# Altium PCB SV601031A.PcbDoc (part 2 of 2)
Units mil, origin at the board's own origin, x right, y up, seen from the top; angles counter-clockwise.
Board outline 4000 x 2000 mil, 6 copper layers (Top Layer, MidLayer1, MidLayer2, Mid-Layer 3, Mid-Layer 4, Bottom Layer), stack 60.8 mil thick; 81 components, 26 nets, 217 pads, 227 vias.
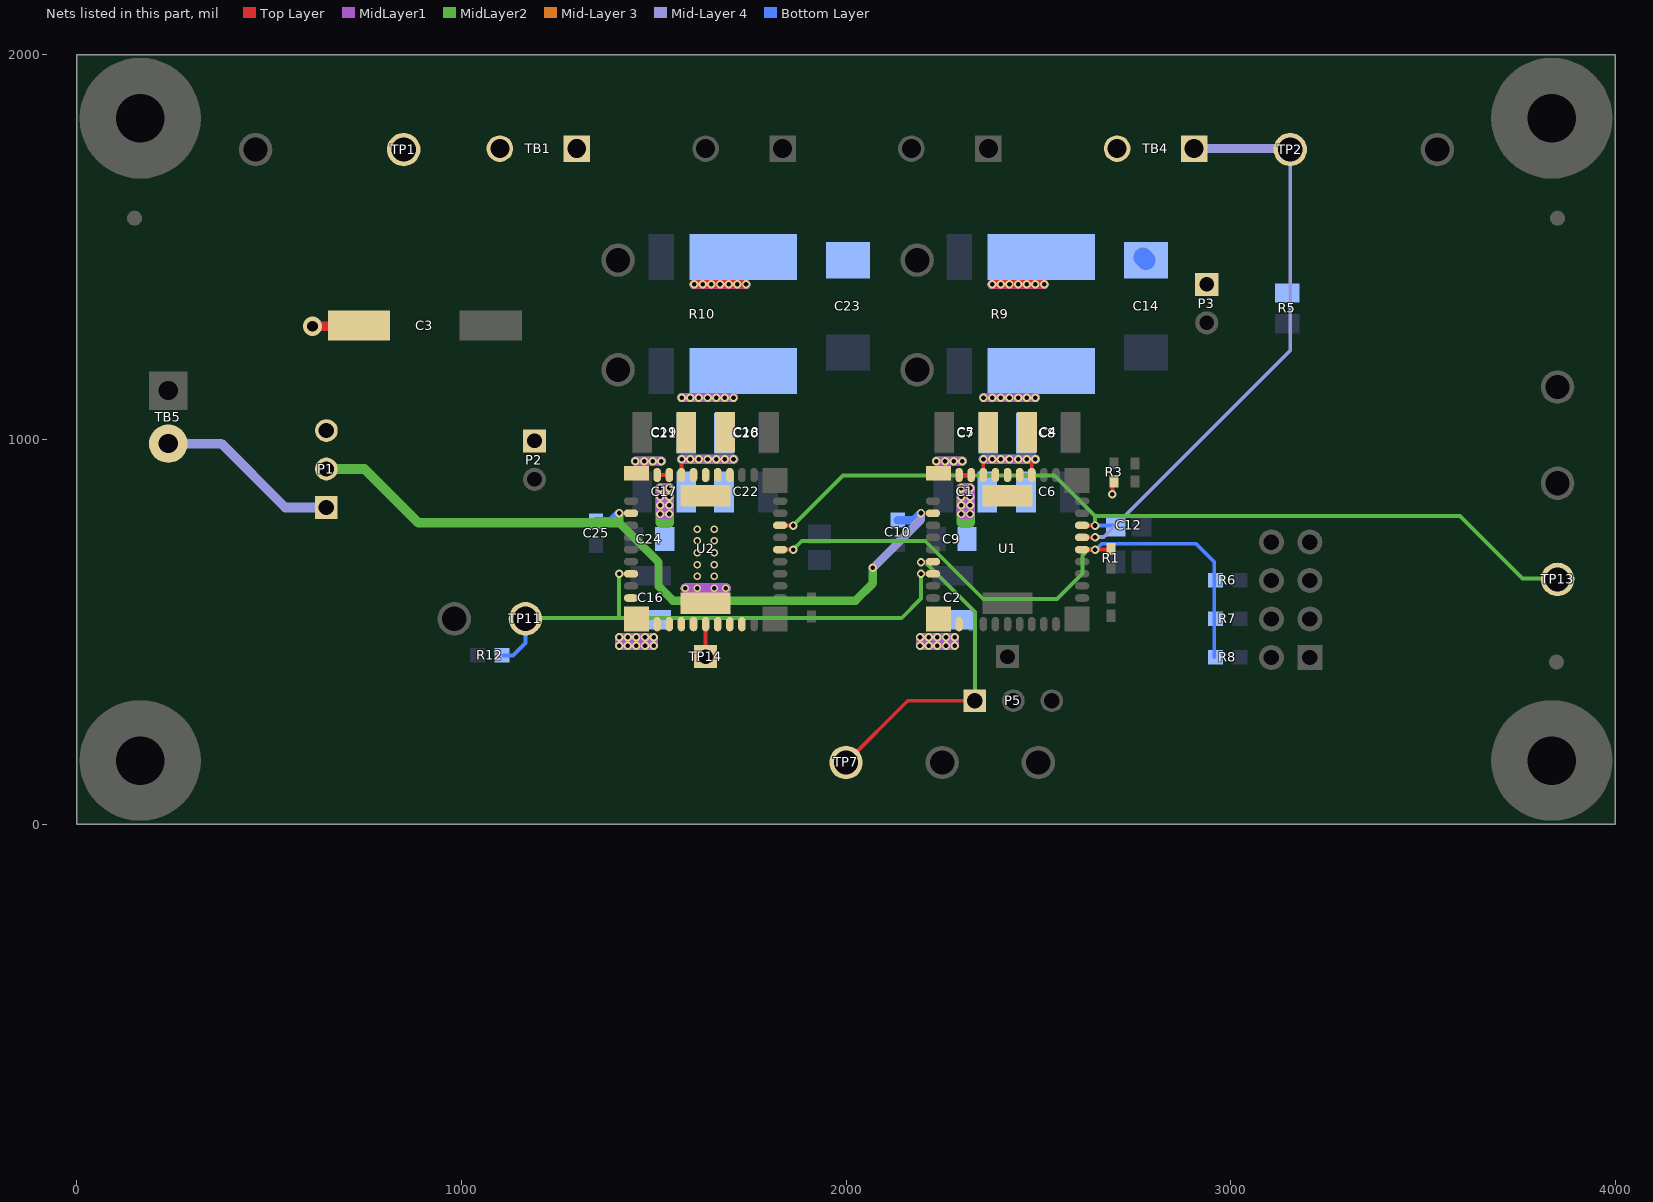
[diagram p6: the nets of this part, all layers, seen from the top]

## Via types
v1: diameter 22/22/22/22/22/22 (per signal layer), hole 12, Top Layer to Bottom Layer, 198 vias
v2: diameter 19.68, hole 11.81, Top Layer to Bottom Layer, 28 vias
v3: diameter 50, hole 28, Top Layer to Bottom Layer, 1 vias

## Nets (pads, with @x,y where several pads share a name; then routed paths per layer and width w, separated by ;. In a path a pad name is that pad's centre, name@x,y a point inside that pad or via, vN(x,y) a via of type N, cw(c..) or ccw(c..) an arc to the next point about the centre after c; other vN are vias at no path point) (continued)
PH2: TP14.1 U2.10 U2.13 U2.14 U2.15 U2.16 U2.17 U2.18 U2.19 U2.42 | length 604.6
  Top Layer w10: TP14.1@1635,443.5 U2.16@1635,519.6
  MidLayer1 w25: v2(1582.15,613.11) v2(1612.85,613.11) v2(1657.15,613.11) v2(1687.85,613.11)
  MidLayer2 w25: v2(1582.15,613.11) v2(1612.85,613.11) v2(1657.15,613.11) v2(1687.85,613.11)
  Mid-Layer 3 w25: v2(1582.15,613.11) v2(1612.85,613.11) v2(1657.15,613.11) v2(1687.85,613.11)
  Mid-Layer 4 w25: v2(1582.15,613.11) v2(1612.85,613.11) v2(1657.15,613.11) v2(1687.85,613.11)
  Bottom Layer w25: v2(1582.15,613.11) v2(1612.85,613.11) v2(1657.15,613.11) v2(1687.85,613.11)
  other v2: 1612.85,643.82 1657.15,643.82 1612.85,674.52 1657.15,674.52 1612.85,705.23 1657.15,705.23 1612.85,735.94 1657.15,735.94 1612.85,766.65 1657.15,766.65
PRE_VOUT: C4.1 C5.1 C6.1 C7.1 C8.1 R9.4 U1.34 U1.35 U1.36 U1.37 U1.38 U1.41 | length 1014.7
  Top Layer w10: U1.38@2357.01,907.4 2357.01,948.5 v1(2357.5,948.5) v1(2380,948.5) v1(2402.5,948.5) v1(2425,948.5) v1(2447.5,948.5) v1(2470,948.5) ; U1.34@2482.99,907.4 2482.99,948.5 v1(2492.5,948.5)
  MidLayer1 w23: v1(2357.5,948.5) v1(2380,948.5) v1(2402.5,948.5) v1(2425,948.5) v1(2447.5,948.5) v1(2470,948.5) v1(2492.5,948.5) ; v1(2357.5,1108.5) v1(2380,1108.5) v1(2402.5,1108.5) v1(2425,1108.5) v1(2447.5,1108.5) v1(2470,1108.5) v1(2492.5,1108.5)
  MidLayer2 w23: v1(2357.5,948.5) v1(2380,948.5) v1(2402.5,948.5) v1(2425,948.5) v1(2447.5,948.5) v1(2470,948.5) v1(2492.5,948.5) ; v1(2357.5,1108.5) v1(2380,1108.5) v1(2402.5,1108.5) v1(2425,1108.5) v1(2447.5,1108.5) v1(2470,1108.5) v1(2492.5,1108.5)
  Mid-Layer 4 w22: v1(2357.5,1108.5) v1(2380,1108.5) v1(2402.5,1108.5) v1(2425,1108.5) v1(2447.5,1108.5) v1(2470,1108.5) v1(2492.5,1108.5)
  Mid-Layer 4 w25: v1(2357.5,948.5) v1(2380,948.5) v1(2402.5,948.5) v1(2425,948.5) v1(2447.5,948.5) v1(2470,948.5) v1(2492.5,948.5)
PRE_VOUT2: C18.1 C19.1 C20.1 C21.1 C22.1 R10.4 U2.34 U2.35 U2.36 U2.37 U2.38 U2.41 | length 986.6
  Top Layer w10: U2.38@1572.01,907.4 1572.01,948.5 v1(1572.5,948.5) v1(1595,948.5) v1(1617.5,948.5) v1(1640,948.5) v1(1662.5,948.5) v1(1685,948.5) v1(1707.5,948.5)
  MidLayer1 w23: v1(1572.5,948.5) v1(1595,948.5) v1(1617.5,948.5) v1(1640,948.5) v1(1662.5,948.5) v1(1685,948.5) v1(1707.5,948.5) ; v1(1572.5,1108.5) v1(1595,1108.5) v1(1617.5,1108.5) v1(1640,1108.5) v1(1662.5,1108.5) v1(1685,1108.5) v1(1707.5,1108.5)
  MidLayer2 w23: v1(1572.5,948.5) v1(1595,948.5) v1(1617.5,948.5) v1(1640,948.5) v1(1662.5,948.5) v1(1685,948.5) v1(1707.5,948.5) ; v1(1572.5,1108.5) v1(1595,1108.5) v1(1617.5,1108.5) v1(1640,1108.5) v1(1662.5,1108.5) v1(1685,1108.5) v1(1707.5,1108.5)
  Mid-Layer 4 w22: v1(1572.5,1108.5) v1(1595,1108.5) v1(1617.5,1108.5) v1(1640,1108.5) v1(1662.5,1108.5) v1(1685,1108.5) v1(1707.5,1108.5)
  Mid-Layer 4 w25: v1(1572.5,948.5) v1(1595,948.5) v1(1617.5,948.5) v1(1640,948.5) v1(1662.5,948.5) v1(1685,948.5) v1(1707.5,948.5)
PVIN: C1.1 C2.1 C3.1 C9.1 C16.1 C17.1 C24.1 P1.3 P2.1 R3.2 TB1.1 TB1.2 TP1.1 U1.1 U1.11 U1.12 U1.39 U1.40 U2.1 U2.11 U2.12 U2.39 U2.40 | length 2262.9
  Top Layer w10: U2.40@1509.02,907.4 U2.39@1540.51,907.4 ; U1.11@2215,533.38 U1.11@2239.88,533.38 ; U1.40@2294.02,907.4 U1.39@2325.51,907.4 ; v1@2692.5,863.5 R3.2@2692.5,888.5
  Top Layer w25: v3@619,1294 731.74,1294 C3.1@733.74,1296
  MidLayer1 w22: v1@2192.5,483.5 v1(2192.5,463.5) v1(2215,463.5) v1(2237.5,463.5) v1(2260,463.5) v1(2282.5,463.5) v1(2282.5,486) v1(2260,486) v1(2237.5,486) v1(2215,486) v1(2192.5,486) ; v1(1410,463.5) v1(1410,486) v1(1432.5,486) v1(1455,486) v1(1477.5,486) v1(1500,486) v1(1500,463.5) v1(1477.5,463.5) v1(1455,463.5) v1(1432.5,463.5) v1(1410,463.5)
  MidLayer1 w23: v1(1452.5,943.5) v1(1520,943.5) ; v1(2235,943.5) v1(2257.5,943.5) v1(2280,943.5) v1(2302.5,943.5)
  MidLayer1 w25: v1@1517.5,870.5 v1(1517.5,851) v1(1517.5,828.5) v1(1517.5,806) v1(1540,806) v1(1540,828.5) v1(1540,851) v1(1540,873.5) v1(1517.5,873.5) ; v1@2300,871 v1(2300,851) v1(2300,828.5) v1(2300,806) v1(2322.5,806) v1(2322.5,828.5) v1(2322.5,851) v1(2322.5,873.5) v1(2300,873.5)
  MidLayer2 w22: v1(2192.5,486) v1(2192.5,463.5) v1(2215,463.5) v1(2237.5,463.5) v1(2260,463.5) v1(2282.5,463.5) v1(2282.5,486) v1(2260,486) v1(2237.5,486) v1(2215,486) v1@2195,486 ; v1(1410,463.5) v1(1410,486) v1(1432.5,486) v1(1455,486) v1(1477.5,486) v1(1500,486) v1(1500,463.5) v1(1477.5,463.5) v1(1455,463.5) v1(1432.5,463.5) v1(1410,463.5)
  MidLayer2 w23: v1(1452.5,943.5) v1(1497.5,943.5) v1(1520,943.5) ; v1(2235,943.5) v1(2257.5,943.5) v1(2280,943.5) v1(2302.5,943.5)
  MidLayer2 w25: v1@1517.5,872.5 v1(1517.5,851) v1(1517.5,828.5) v1(1517.5,806) 1517.5,783.5 1540,783.5 v1(1540,806) v1(1540,828.5) v1(1540,851) v1(1540,873.5) v1(1517.5,873.5) ; v1@2300,872 v1(2300,851) v1(2300,828.5) v1(2300,806) 2300,783.5 2322.5,783.5 v1(2322.5,806) v1(2322.5,828.5) v1(2322.5,851) v1(2322.5,873.5) v1(2300,873.5)
  Bottom Layer w22: v1(2235,943.5) v1(2257.5,943.5) v1(2280,943.5) v1(2302.5,943.5)
  other v1: 2692.5,857.5 1475,943.5
  other v3: 613,1294
PWRGD: R12.1 TP11.1 U1.8 U2.8 | length 1421.9
  Top Layer w10: v1@1410,650.51 U2.8@1441.1,650.51 ; v1@2195.49,650.51 U1.8@2226.1,650.51
  MidLayer2 w10: TP11.1@1169,536 1410,536 ; v1(1410,651) 1410,536 ; v1(2195,651) 2195,586 2145,536 1410,536
  Bottom Layer w10: R12.1@1109,438.5 1134,438.5 1166.5,471 TP11.1@1166.5,533.5
SS/TR: C12.1 TP13.1 U1.28 U2.28 | length 2346.7
  Top Layer w10: U2.28@1828.9,776.49 v1@1862.5,776.49 ; U1.28@2613.9,776.49 v1@2647.01,776.49
  MidLayer2 w10: v1(1862.5,776) 1992.5,906 2542.5,906 2647.5,801 ; v1(2647.5,776) 2647.5,801 ; TP13.1@3880,636 3890,638.5 3758.5,638.5 3596,801 2647.5,801
  Bottom Layer w10: v1(2647.5,776) C12.1@2700,776
SYNC_OUT: P5.1 TP7.1 U1.7 | length 874.3
  Top Layer w10: TP7.1@2000,160 2160.5,320.5 P5.1@2335,320.5 ; v1(2195,681) 2196,682 U1.7@2226.1,682
  MidLayer2 w10: v1(2195,681) 2205,681 2335,551 P5.1@2335,320.5 P5.1@2335,303.5
VADJ: R1.2 R6.2 R7.2 R8.2 U1.26 U2.26 | length 1633.5
  Top Layer w10: U2.26@1828.9,713.5 v1(1862.5,713.5) ; U1.26@2613.9,713.5 v1(2647.5,713.5) 2692.5,713.5 R1.2@2692.5,716
  MidLayer2 w10: v1(1862.5,713.5) 1885,736 2206,736 2357,585 2549,585 2615,651 2615,698.5 2630,713.5 v1(2647.5,713.5)
  Bottom Layer w10: v1@2650,713.5 2665,728.5 2910,728.5 2957.5,681 R8.2@2957.5,433.5
VBIAS: P1.1 TB5.2 | length 479.8
  Mid-Layer 4 w25: TB5.2@238,989 376,989 542,823 P1.1@649,823
VIN: C10.1 C25.1 P1.2 U1.3 U2.3 | length 2075.2
  Top Layer w10: v1@1410.51,807.99 U2.3@1441.1,807.99 ; v1@2195,807.99 U1.3@2226.1,807.99
  MidLayer2 w22: v1(1410,808.5) 1410,783.5 1512.5,681 1512.5,618.5 1550,581 2025,581 2070,626 v1(2070,666)
  MidLayer2 w25: P1.2@649,923 748,923 887.5,783.5 1410,783.5
  Mid-Layer 4 w22: v1(2070,666) 2195,791 v1(2195,808.5)
  Bottom Layer w22: C25.1@1350,787.5 1389,787.5 v1(1410,808.5) ; C10.1@2135,790 2176.5,790 v1(2195,808.5)
VOUT: C14.1 C23.1 P3.1 R5.1 R9.2 R10.2 TB4.1 TB4.2 TP2.1 U1.27 | length 3157.1
  Top Layer w10: U1.27@2613.9,745 2647.5,745 v1(2647.5,746)
  Top Layer w22: v1(1605,1403) v1(1627.5,1403) v1(1650,1403) v1(1672.5,1403) v1(1695,1403) v1(1717.5,1403) v1(1740,1403) ; v1(2380,1403) v1(2402.5,1403) v1(2425,1403) v1(2447.5,1403) v1(2470,1403) v1(2492.5,1403) v1(2515,1403)
  MidLayer1 w23: v1(1605,1403) v1(1627.5,1403) v1(1650,1403) v1(1672.5,1403) v1(1695,1403) v1(1717.5,1403) v1(1740,1403) ; v1(2380,1403) v1(2402.5,1403) v1(2425,1403) v1(2447.5,1403) v1(2470,1403) v1(2492.5,1403) v1(2515,1403)
  MidLayer2 w23: v1(1605,1403) v1(1627.5,1403) v1(1650,1403) v1(1672.5,1403) v1(1695,1403) v1(1717.5,1403) v1(1740,1403) ; v1(2380,1403) v1(2402.5,1403) v1(2425,1403) v1(2447.5,1403) v1(2470,1403) v1(2492.5,1403) v1(2515,1403)
  Mid-Layer 3 w23: v1(1605,1403) v1(1627.5,1403) v1(1650,1403) v1(1672.5,1403) v1(1695,1403) v1(1717.5,1403) v1(1740,1403) ; v1(2380,1403) v1(2402.5,1403) v1(2425,1403) v1(2447.5,1403) v1(2470,1403) v1(2492.5,1403) v1(2515,1403)
  Mid-Layer 4 w10: v1(2647.5,746) 2670,746 3155,1231 TP2.1@3155,1753.5
  Mid-Layer 4 w23: v1(1605,1403) v1(1627.5,1403) v1(1650,1403) v1(1672.5,1403) v1(1695,1403) v1(1717.5,1403) v1(1740,1403) ; v1(2380,1403) v1(2402.5,1403) v1(2425,1403) v1(2447.5,1403) v1(2470,1403) v1(2492.5,1403) v1(2515,1403) ; TB4.1@2895,1756 3152.5,1756 TP2.1@3155,1753.5
  Bottom Layer w23: v1(1605,1403) v1(1627.5,1403) v1(1650,1403) v1(1672.5,1403) v1(1695,1403) v1(1717.5,1403) v1(1740,1403) ; v1(2380,1403) v1(2402.5,1403) v1(2425,1403) v1(2447.5,1403) v1(2470,1403) v1(2492.5,1403) v1(2515,1403)
  Bottom Layer w50: C14.1@2772.5,1473.5 C14.1@2780,1466
pads on no net: FID1.1 FID2.1 FID3.1 H1.1 H2.1 H3.1 H4.1 LBL1.0 P4.8 SH-J1.0 SH-J2.0 SH-J3.0 U1.4 U1.5 U1.6 U1.9 U1.24 U2.4 U2.5 U2.6 U2.7 U2.9 U2.24 U2.27

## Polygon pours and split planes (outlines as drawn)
AGND on Top Layer "Top-AGND" (solid, remove dead copper, pour order 119): 20,1978 3980,1978 3980,18 20,18
PGND on Top Layer "Top-PGND 1" (solid, remove dead copper, pour order 118): 20,1973 20,967 2632.5,967 2662.5,999.19 2662.5,1973
PGND on Top Layer "Top-PGND" (solid, remove dead copper, pour order 117): 1719.74,927.56 1719.74,822.3 1712.74,815.3 1562.74,815.3 1562.74,792.8 1712.74,792.8 1719.74,785.8 1719.74,587.8 1751.24,556.8 1751.24,442.8 1867.74,442.8 1867.74,565.3 1807.74,565.3 1797.74,575.3 1797.74,856.8 2102.74,856.8 2102.74,1072.8 1745.24,1072.8 1745.24,952.56
PVIN on Top Layer "Top-PVIN 1" (solid, remove dead copper, pour order 116): 1328.71,956.78 1528.08,956.78 1553,931.42 1553,619.51 1541.54,607.84 1473.25,607.84 1473.25,850.27 1464.28,859.4 1410.95,859.4 1410.95,566.26 1513.13,566.26 1513.13,442 1328.71,442
PVIN on Top Layer "Top-PVIN 2" (solid, remove dead copper, pour order 115): 2113,956 2312.83,956 2335.31,933.24 2335.31,617.1 2326.32,607.99 2257.88,607.99 2257.88,849.78 2248.88,858.88 2195.43,858.88 2195.43,566.52 2297.84,566.52 2297.84,442.59 2113,442.59
PGND on Top Layer "Top-PGND 2" (solid, remove dead copper, pour order 114): 2504.63,928.06 2504.63,822.76 2497.63,815.76 2345.13,815.76 2345.13,793.26 2497.63,793.26 2504.63,786.26 2504.63,588.26 2536.13,557.26 2536.13,443.26 2652.63,443.26 2652.63,565.76 2592.63,565.76 2582.63,575.76 2582.63,857.26 2662.63,857.26 2662.63,1073.26 2530.13,1073.26 2530.13,953.06
PRE_VOUT2 on Top Layer "Top-$$$2" (solid, remove dead copper, pour order 113): 1563,822 1563,934.5 1533,964.5 1533,1129.5 1735.5,1129.5 1735.5,959.5 1708,932 1708,822
PRE_VOUT on Top Layer "Top-$$$" (solid, remove dead copper, pour order 112): 2347.5,823.15 2347.5,935.65 2317.5,965.65 2317.5,1130.65 2520,1130.65 2520,960.65 2492.5,933.15 2492.5,823.15
PH2 on Top Layer "Top-PH2" (solid, remove dead copper, pour order 57): 1711,580 1711,785.5 1563.5,785.5 1563.5,607 1553.5,597 1423.5,597 1423.5,577 1521.5,577 1531.5,567 1531.5,500.5 1740.5,500.5 1740.5,550.5
PH on Top Layer "Top-PH" (solid, remove dead copper, pour order 56): 2495,580.5 2495,786 2347.5,786 2347.5,607.5 2337.5,597.5 2207.5,597.5 2207.5,577.5 2305.5,577.5 2315.5,567.5 2315.5,501 2524.5,501 2524.5,551
PGND on MidLayer1 "Layer 2-PGND" (solid, remove dead copper, pour order 122): 20,19 3980,19 3980,1979 20,1979
PH on MidLayer1 "Layer 2-PH" (solid, remove dead copper, pour order 121): 2385,782.2 2455,782.2 2455,601 2385,601
PH2 on MidLayer1 "Layer 2-PH2" (solid, remove dead copper, pour order 120): 1600,781 1670,781 1670,601 1600,601
PGND on MidLayer2 "Layer 3-PGND" (solid, remove dead copper, pour order 125): 20,19 3980,19 3980,1979 20,1979
PH on MidLayer2 "Layer 3-PH" (solid, remove dead copper, pour order 124): 2385,782 2455,782 2455,602 2385,602
PH2 on MidLayer2 "Layer 3-PH2" (solid, remove dead copper, pour order 123): 1600,782 1670,782 1670,602 1600,602
AGND on Mid-Layer 4 "Layer 5-AGND" (solid, remove dead copper, pour order 136): 3980,985 2193,985 2193,20 3980,20
PVIN on Mid-Layer 4 "Layer 5-PVIN" (solid, remove dead copper, pour order 135): 20,-107 2280,-107 2280,358.85 2355,438.71 2355,792.8 2379.75,819.37 2731.25,819.37 2832.5,925.85 3980,925.85 3980,1980 20,1980
PH on Mid-Layer 4 "Layer 5-PH" (solid, remove dead copper, pour order 134): 2385,781 2455,781 2455,602 2385,602
PH2 on Mid-Layer 4 "Layer 5-PH2" (solid, remove dead copper, pour order 133): 1600,781 1600,602 1667.5,602 1667.5,781
PGND on Bottom Layer "Bottom-PGND" (solid, remove dead copper, pour order 146): 18,1981 3978,1981 3978,21 18,21
VOUT on Bottom Layer "Bottom-VOUT" (solid, remove dead copper, pour order 145): 1403,1981 1403,1422 1533.56,1422 1563.68,1387.6 2819.02,1387.6 2864.22,1336 3989,1336 3989,1981
PRE_VOUT2 on Bottom Layer "Bottom-$$$2" (solid, remove dead copper, pour order 144): 1560,1312 1560,944.87 1572.6,932.38 1615.43,932.38 1625.51,922.39 1625.51,810 1728.82,810 1746.46,827.48 1746.46,1064.75 1766.61,1084.73 1849.76,1084.73 1880,1114.7 1880,1312
PRE_VOUT on Bottom Layer "Bottom-$$$1" (solid, remove dead copper, pour order 143): 2345,1312 2345,944.87 2357.6,932.38 2400.45,932.38 2410.53,922.39 2410.53,810 2513.87,810 2531.52,827.48 2531.52,1064.75 2551.68,1084.73 2627.3,1084.73 2652.5,1109.7 2652.5,1312
PVIN on Bottom Layer "Bottom-PVIN 1" (solid, remove dead copper, pour order 142): 1615,921.36 1567.5,921.36 1535,954.46 1440,954.46 1440,929 1495,929 1502.5,921.36 1502.5,712.56 1507.5,707.46 1557.5,707.46 1567.5,717.65 1567.5,804.23 1572.5,809.32 1615,809.32
PVIN on Bottom Layer "Bottom-PVIN 3" (solid, remove dead copper, pour order 141): 2397.21,921 2350.26,921 2318.13,954.1 2224.21,954.1 2224.21,928.64 2278.59,928.64 2286,921 2286,712.2 2290.94,707.1 2340.37,707.1 2350.26,717.29 2350.26,803.87 2355.2,808.96 2397.21,808.96
PVIN on Bottom Layer "Bottom-PVIN 2" (solid, remove dead copper, pour order 140): 2180,557 2180,453 2340,453 2340,557
PVIN on Bottom Layer "Bottom-PVIN" (solid, remove dead copper, pour order 139): 1397.5,557 1397.5,453 1555,453 1555,557
PH2 on Bottom Layer "Bottom-PH2" (solid, remove dead copper, pour order 138): 1670,780 1600,780 1600,603 1670,603
PH on Bottom Layer "Bottom-PH" (solid, remove dead copper, pour order 137): 2455,780 2385,780 2385,603 2455,603
PVIN on Mid-Layer 3 "Layer 4-PVIN" (solid, remove dead copper, pour order 131): 1512.5,1980 20,1980 20,-109 2280,-109 2280,365.23 2340,429.26 2340,800.77 2377.5,840.79 2715,840.79 2715,1387.72 1517.5,1387.72 1512.5,1393.05
AGND on Mid-Layer 3 "Layer 4-AGND" (solid, remove dead copper, pour order 132): 20,20 3980,20 3980,1977.5 20,1977.5
VOUT on Mid-Layer 3 "Layer 4-VOUT" (solid, remove dead copper, pour order 130): 1517.5,1977.5 1517.5,1370.48 1537.5,1348 3975,1348 3975,1977.5
PRE_VOUT on Mid-Layer 3 "Layer 4-$$$" (solid, remove dead copper, pour order 129): 2340,938 2510,938 2510,1119 2340,1119
PRE_VOUT2 on Mid-Layer 3 "Layer 4-$$$2" (solid, remove dead copper, pour order 128): 1557.5,938 1557.5,1119 1722.5,1119 1722.5,938
PH on Mid-Layer 3 "Layer 4-PH" (solid, remove dead copper, pour order 127): 2385,779.51 2455,779.51 2455,602 2385,602
PH2 on Mid-Layer 3 "Layer 4-PH2" (solid, remove dead copper, pour order 126): 1600,779 1670,779 1670,602 1600,602

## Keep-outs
Keep-Out Layer:
  the board outline again, w4
  text ".Layer_Name" at -38,-1627.49 h60

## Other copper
Top Layer:
  text "Top Layer" at -38,-1627.49 h60
MidLayer1:
  text "MidlLayer1" at -9,-1633 h62.5
MidLayer2:
  text "MidlLayer2" at -28,-1633 h62.5
Mid-Layer 3:
  pour cut-out: 3097.5,1811 3212.5,1811 3212.5,1696 3097.5,1696 3097.5,1811
  text "MidlLayer3" at 18,-1633 h62.5
Mid-Layer 4:
  text "MidlLayer4" at 2,-1641 h62.5
Bottom Layer:
  pour cut-out: 3097.5,1811 3212.5,1811 3212.5,1696 3097.5,1696 3097.5,1811
  text "Bottom Layer" at -38,-1627.49 h60

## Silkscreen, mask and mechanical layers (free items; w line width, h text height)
Top Overlay:
  region: 3348.5,118 3348.5,208 3601.5,208 3601.5,118
  lines w5: 1412.5,491 1857.5,491 1857.5,504 1942,504 1942,622 1857.5,622 1857.5,1086 1412.5,1086 1412.5,491 ; 2197.5,491 2642.5,491 2642.5,506 2721,506 2721,750 2642.5,750 2642.5,854 2785,854 2785,974 2642.5,974 2642.5,1086 2197.5,1086 2197.5,491
  lines w8: 1325,1243 1325,1224 1335,1224 ; 1325,1398 1325,1417 1338,1417 ; 1477,1417 1490,1417 1490,1398 ; 1480,1224 1490,1224 1490,1243 ; 2102,1243 2102,1224 2112,1224 ; 2102,1398 2102,1417 2115,1417 ; 2254,1417 2267,1417 2267,1398 ; 2257,1224 2267,1224 2267,1243
  text "PGND" at 378,1840 h50
  text "PVIN" at 782,1840 h50
  text "VOUT" at 3067,1840 h50
  text "AGND" at 3445,1840 h50
  text "PVIN" at 1152.87,1492 h50
  text "VOUT" at 2705,1490 h50
  text "PGND" at 1658,1487 h50
  text "PGND" at 2288,1487 h50
  text "C3" at 635,1465 h50
  text "-" at 1267.86,1434.5 h40
  text "-" at 2047.86,1434.5 h40
  text "VOUT" at 3011.11,1377 h50
  text "+" at 658,1366 h30
  text "SLAVE" at 1304,1332 h50
  text "MASTER" at 2067,1332 h50
  text "PGND" at 3011.16,1277 h50
  text "CURRENT" at 1256,1263 h50
  text "CURRENT" at 2047,1263 h50
  text "INH/UVLO" at 3661,1227 h50
  text "+" at 1264,1169 h40
  text "+" at 2043,1165 h40
  text "SLAVE" at 1548,1150 h50
  text "MASTER" at 2294,1150 h50
  text "VBIAS" at 376,1103 h50
  text "PVIN" at 740.37,1007 h50
  text "AGND" at 3753,976 h50
  text "PVIN" at 988,969 h50
  text "PGND" at 377,965 h50
  text "VIN" at 733.17,907 h50
  text "1" at 1366,896 h50
  text "1" at 2151,891 h50
  text "VOUT" at 3067,891 h50
  text "PGND" at 952,866 h50
  text "SELECT" at 3038,816 h50
  text "VBIAS" at 734,792 h50
  text "SS/TR" at 3741,725 h50
  text "PWRGD" at 855,710 h50
  text "0.6V" at 3292.5,708 h50
  text "VIN" at 602,665 h50
  text "PULL_UP" at 822,636 h50
  text "PWRGD" at 1144,636 h50
  text "0.9V" at 3292.5,608 h50
  text "SELECT" at 537,597 h50
  text "1.2V" at 3292.5,508 h50
  text "1.8V" at 3292.5,408 h50
  text "PH2" at 1459,392 h45
  text "PH1" at 2260,392 h45
  text "SLAVE_SYNC 180" at 1624,275 h50
  text "SLAVE_CLK_IN" at 2612,275 h50
  text "LMZ31710X2EVM" at 454,158 h50
  text "SV601031" at 2983,136 h50
  text "REV A" at 3377,45 h50
  text "SYNC_OUT" at 1727,24 h50
  text "CLK_IN" at 2395,24 h50
  text "AGND" at 2157,23 h50
  text ".Layer_Name" at -38,-1627.49 h60
Bottom Overlay:
  text ".Layer_Name" at -38,-1627.49 h60
Top Paste:
  text ".Layer_Name" at -38,-1627.49 h60
Bottom Paste:
  text ".Layer_Name" at -38,-1627.49 h60
Top Solder:
  text ".Layer_Name" at -38,-1627.49 h60
  text ".Layer_Name" at -38,-1627.49 h60
Bottom Solder:
  text ".Layer_Name" at -38,-1627.49 h60
Drill Guide:
  text ".Layer_Name" at -38,-1627.49 h60
M1 Board Outline:
  the board outline again, w4
  text ".Layer_Name" at -38,-1627.49 h60
M2 Board Dimensions:
  rectangle: -490.5,-1179.5 -115.5,-1054.5
  rectangle: -615.5,-1054.5 -490.5,-929.5
  lines w7: -615.5,-1054.5 384.5,-1054.5 ; -490.5,-1179.5 -490.5,-929.5 ; -365.5,-1179.5 -365.5,-929.5 ; -115.5,-1179.5 -115.5,-929.5 ; 134.5,-1179.5 134.5,-929.5 ; -615.5,-1179.5 -615.5,-929.5 384.5,-929.5 384.5,-1179.5 -615.5,-1179.5
  lines w10: -615.5,-1244.5 -615.5,-1224.5 ; -555.5,-1254.5 -615.5,-1234.5 ; -555.5,-1214.5 -615.5,-1234.5 ; -391.42,-1234.5 -615.5,-1234.5 ; -120,60 -100,0 ; -120,1940 -100,2000 ; -110,0 -90,0 ; -110,2000 -90,2000 ; -100,719.09 -100,0 ; -100,1280.91 -100,2000 ; -80,60 -100,0 ; -80,1940 -100,2000 ; 0,2090 0,2110 ; 60,2080 0,2100 ; 60,2120 0,2100 ; 160.42,-1234.5 384.5,-1234.5 ; 324.5,-1254.5 384.5,-1234.5 ; 324.5,-1214.5 384.5,-1234.5 ; 384.5,-1244.5 384.5,-1224.5 ; 1719.09,2100 0,2100 ; 2280.91,2100 4000,2100 ; 3940,2080 4000,2100 ; 3940,2120 4000,2100 ; 4000,2090 4000,2110
  text "4000 (mil)" at 1729.09,2064.01 h60
  text "C10" at 2176,742 h32.5
  text "2000 (mil)" at -64.01,729.09 h60 r90
  text "R12" at 1109,422 h32.5
  text "1000 (mil)" at -381.42,-1270.49 h60
  text ".Layer_Name" at -38,-1627.49 h60
M3 3D STEP Top:
  text ".Layer_Name" at -38,-1627.49 h60
M4 3D STEP Bottom:
  text ".Layer_Name" at -38,-1627.49 h60
M5 Assembly Top:
  lines w10: -907,-1699.17 5693,-1699.17 ; -907,-1495.83 5695,-1495.83 ; -907,-1292.5 -907,-1902.5 3098,-1902.5 5695,-1902.5 5695,-1292.5 -906.5,-1292.5 -906.5,-1902.5 669,-1902.5 ; 1558,-1902.5 1558,-1292.5 ; 2825,-1495.83 2825,-1292.5 ; 3665,-1495.83 3665,-1292.5 ; 4287,-1909 4287,-1706.17
  text "COMPONENTS MARKED 'DNP' SHOULD NOT BE POPULATED." at 538.5,-1087.5 h60
  text "ASSEMBLY VARIANT:" at 538,-1203 h60
  text ".VariantName" at 1574,-1203 h60
  text "PCB VIEWED FROM TOP SIDE" at -843.5,-1424.67 h60
  text "BOARD #:" at 1633,-1424.67 h60
  text ".PRJ_Number" at 2178.5,-1424.67 h60
  text "REV:" at 3023,-1424.67 h60
  text ".PCB_Rev" at 3314.5,-1424.67 h60
  text "SVN REV:" at 3861,-1424.67 h60
  text ".VersionControl_RevNumber" at 4367,-1424.67 h60
  text "IGNORE ->" at -843.5,-1627.49 h60
  text "PLOT NAME =" at -843.5,-1833.34 h60
  text ".plot_File_Name" at -38,-1833.34 h60
  text "GENERATED    :" at 1635,-1833.34 h60
  text ".Print_Date" at 2504.5,-1833.34 h60
  text ".Print_Time" at 3233.5,-1833.34 h60
  text "TEXAS INSTRUMENTS" at 4498,-1833.34 h60
M6 Assembly Bottom:
  lines w10: -907.5,-1496.33 5694.5,-1496.33 ; -905.5,-1699.67 5694.5,-1699.67 ; 500.5,-1909.5 500.5,-1706.67 ; 1122.5,-1496.33 1122.5,-1293 ; 1962.5,-1496.33 1962.5,-1293 ; 3229.5,-1903 3229.5,-1293 ; 4118.5,-1903 5694,-1903 5694,-1293 -907.5,-1293 -907.5,-1903 1689.5,-1903 5694.5,-1903 5694.5,-1293
  text "COMPONENTS MARKED 'DNP' SHOULD NOT BE POPULATED." at 5487,-1087 h60
  text ".VariantName" at 4443,-1203 h60
  text "ASSEMBLY VARIANT:" at 5482,-1203 h60
  text ".VersionControl_RevNumber" at 420.5,-1425.17 h60
  text "SVN REV:" at 926.5,-1425.17 h60
  text ".PCB_Rev" at 1473,-1425.17 h60
  text "REV:" at 1764.5,-1425.17 h60
  text ".PRJ_Number" at 2609,-1425.17 h60
  text "BOARD #:" at 3154.5,-1425.17 h60
  text "PCB VIEWED FROM BOTTOM SIDE" at 5631,-1425.17 h60
  text "IGNORE ->" at 1932.85,-1627.49 h60
  text "TEXAS INSTRUMENTS" at 289.5,-1833.84 h60
  text ".Print_Time" at 1554,-1833.84 h60
  text ".Print_Date" at 2283,-1833.84 h60
  text "GENERATED    :" at 3152.5,-1833.84 h60
  text ".plot_File_Name" at 4825.5,-1833.84 h60
  text "PLOT NAME =" at 5631,-1833.84 h60
M9 Title Sheet:
  drawing of 57 lines, arcs and shapes, not listed
  text "1" at 124.84,7267.5 h70
  text "2" at 2620.5,7267.5 h70
  text "3" at 5109.84,7267.5 h70
  text "4" at 7616.51,7267.5 h70
  text "5" at 10115.5,7267.5 h70
  text "6" at 12620.5,7267.5 h70
  text "A" at -1031.5,6124.5 h70
  text "A" at 13768.5,6124.5 h70
  text "B" at -1031.5,3744.5 h70
  text "B" at 13768.5,3744.5 h70
  text "C" at -1031.5,1369.5 h70
  text "C" at 13768.5,1369.5 h70
  text "PROJECT TITLE:" at 10728.5,-491.5 h45
  text "LMZ31710EVM" at 10778.5,-624.83 h70
  text "DESIGNED FOR:" at 10728.5,-792.5 h45
  text "Public Release" at 10778.5,-932.5 h70
  text "D" at -1031.5,-1000.5 h70
  text "D" at 13768.5,-1000.5 h70
  text "FILE NAME:" at 10728.5,-1092.5 h45
  text "SV601031A.PcbDoc" at 10778.5,-1212.5 h70
  text "Texas Instruments (TI) and/or its licensors do not warrant the accuracy or completeness of this specification" at 5759,-1374.34 h45
  text "ENGINEER:" at 10728.5,-1382.5 h45
  text "LAYOUT BY:" at 12233.5,-1382.5 h45
  text "or any information contained therein. TI and/or its licensors do not warrant that this design will meet" at 5714.01,-1487 h45
  text "Jason Arrigo" at 10778.5,-1537.49 h70
  text "Jim McTeague" at 12284,-1537.49 h70
  text "the specifications, will be suitable for your application or fit for any particular purpose, or will operate in" at 5714.01,-1599.67 h45
  text ".Layer_Name" at -38,-1627.49 h60
  text "ALTIUM DESIGNER VERSION:" at 12233.5,-1692.5 h45
  text "an implementation. TI and/or its licensors do not warrant that the design is production worthy. You should" at 5714.01,-1712.33 h45
  text "completely validate and test your design implementation to confirm the system functionality for your application." at 5759,-1825 h45
  text ".print_Scale" at 10778.5,-1825.83 h70
  text ".Application_BuildNumber" at 12284,-1825.83 h70
  text "1" at 124.84,-2032.5 h70
  text "2" at 2620.5,-2032.5 h70
  text "3" at 5109.84,-2032.5 h70
  text "4" at 7616.51,-2032.5 h70
  text "5" at 10115.5,-2032.5 h70
  text "6" at 12620.5,-2032.5 h70
M10 Fab Notes:
  drawing of 212 lines, arcs and shapes, not listed
  text "DESIGN INFORMATION" at 11766.02,6041 h60
  text "(REFER ALSO ARRAY/PANEL PROFILING INFORMATION)" at 11404.46,5879.29 h60
  text "BOARD SIZE" at 10718.46,5875 h60
  text "2000MIL" at 11180.78,5747.18 h60
  text "X" at 11686.46,5747.18 h60
  text "4000MIL" at 11917.78,5747.18 h60
  text "Number of Layers :" at 11121.46,5550 h60
  text "6" at 12216.27,5540 h60
  text "MIN. TRACK WIDTH:" at 11121.46,5411 h60
  text "8" at 12217.7,5411 h60
  text "MIL" at 12372.46,5411 h60
  text "MIN. CLEARANCE:" at 11121.46,5279 h60
  text "8" at 12217.7,5279 h60
  text "MIL" at 12372.46,5279 h60
  text "MIN. VIA PAD SIZE:" at 11121.46,5147 h60
  text "22" at 12187.71,5147 h60
  text "MIL" at 12372.46,5147 h60
  text "0.05mm (2MIL)" at 11816.46,5005.29 h60
  text "MINIMUM ANNULAR RING" at 10792.23,5001 h60
  text "EXTERNAL" at 12524.46,5001 h60
  text "PER" at 10992.23,4883 h60
  text "IPC-D-275 CLASS 2 LEVEL C" at 11212.23,4883 h60
  text "MIL, HOLES" at 12700.46,4770.71 h60
  text "+/-" at 12308,4770 h60
  text "+/-" at 13162,4770 h60
  text "REGISTRATION TOLERANCES:" at 10792.23,4765 h60
  text "METAL" at 11992,4765 h60
  text "5" at 12568.2,4765 h60
  text "3" at 13401.2,4765 h60
  text "MIL" at 13517.46,4765 h60
  text "MATERIAL:" at 10717.46,4555.54 h60
  text "FR-4 High Tg" at 11703.9,4415.21 h60
  text "FR-408" at 11138.46,4406.64 h60
  text "X" at 11550.46,4406.64 h60
  text "OTHER" at 12626.46,4406.64 h60
  text "62 MIL (1.6mm) +/-10%" at 11458.56,4243.92 h60
  text "THICKNESS:" at 10792.23,4239.64 h60
  text "X" at 11330.4,4239.64 h60
  text "OTHER" at 12743.46,4239.64 h60
  text "TOLERANCE:" at 10792.23,4081.64 h60
  text "X" at 11631.53,4081.64 h60
  text "ANSI IPC-6012 TYPE 3 CLASS 2" at 11818.48,4081.64 h60
  text "OTHER +/-" at 11818.46,3925.64 h60
  text "BOW & TWIST:" at 10792.23,3768.64 h60
  text "X" at 11631.53,3768.64 h60
  text "ANSI IPC-6012 TYPE 3 CLASS 2" at 11818.48,3768.64 h60
  text "OTHER +/-" at 11818.46,3610.13 h60
  text "COPPER THICKNESS (FINISHED):" at 10717.46,3474.64 h60
  text "1.4MIL (1oz)" at 11597.46,3321.92 h60
  text "2MIL (1.4oz)" at 12364.46,3321.92 h60
  text "2.8MIL (2oz)" at 13091.46,3321.92 h60
  text "OUTER:" at 11074.46,3317.64 h60
  text "X" at 12965,3317 h60
  text "1.4MIL (1oz)" at 11597.46,3164.92 h60
  text "2.8MIL (2oz)" at 12364.46,3164.92 h60
  text "N/A" at 13091,3165.29 h60
  text "X" at 12233,3162 h60
  text "INNER SIGNAL:" at 10785.38,3160.64 h60
  text "DRILLING:" at 10717.46,3021.64 h60
  text "REFERENCE:" at 10792.23,2904.64 h60
  text "X" at 11440.46,2904.64 h60
  text "AS SHOWN" at 11627.46,2904.64 h60
  text "X" at 12341.46,2904.64 h60
  text "NC_DRILL FILES" at 12478.46,2904.64 h60
  text "PTH MIN COPPER THICKNESS:" at 10792.23,2746.64 h60
  text "X" at 12142.46,2746.64 h60
  text "1MIL" at 12279.46,2746.64 h60
  text "OTHER" at 12776.46,2746.64 h60
  text "BOARD FINISH:" at 10717.46,2587.64 h60
  text "SILKSCREEN:" at 10872.68,2469.64 h60
  text "X" at 11821.46,2469.64 h60
  text "TOP" at 11947.46,2469.64 h60
  text "X" at 12331.46,2469.64 h60
  text "BOTTOM" at 12458.46,2469.64 h60
  text "SILKSCREEN COLOR:" at 10872.68,2302.64 h60
  text "X" at 11820.42,2302.64 h60
  text "WHITE" at 11947.46,2302.64 h60
  text "OTHER" at 12458.46,2302.64 h60
  text "SOLDER RESIST COLOR:" at 10872.68,2132.64 h60
  text "X" at 11440.42,1973.44 h60
  text "GREEN" at 11567.46,1973.44 h60
  text "BLUE" at 12158.46,1973.44 h60
  text "OTHER" at 12696.46,1973.44 h60
  text "IMMERSION GOLD (ENIG)" at 11778.46,1784.92 h60
  text "ENEPIG" at 13116,1781.64 h60
  text "SURFACE FINISH:" at 10717.46,1780.64 h60
  text "IMM. TIN/SILVER OR EQUIV" at 11047,1623.64 h60
  text "OTHER" at 12478.46,1623.64 h60
  text "X" at 10884,1618 h60
  text "ARRAY/PANEL:" at 10717.46,1444.64 h60
  text "CUT AND TRIM PER MECH LAYER 1" at 11778.46,1440.35 h60
  text "N.C. ROUTE" at 11778.46,1288.64 h60
  text "X" at 12457.46,1288.64 h60
  text "V. SCORE" at 12644.46,1288.64 h60
  text "CERTIFICATION:" at 10717.46,1151.64 h60
  text "MATERIALS AND WORKMANSHIP FOR ALL PCBS" at 11442.46,1151.64 h60
  text "TO MEET OR EXCEED THE REQUIREMENTS OF:" at 11442.46,1053.64 h60
  text "X" at 11068.96,917.13 h60
  text "ANSI IPC-A-600F CLASS ->" at 11207.96,917.13 h60
  text "X" at 12847.02,917.13 h60
  text "2" at 12965.96,917.14 h60
  text "1" at 12650.96,915.64 h60
  text "3" at 13319.96,915.64 h60
  text "X" at 11071.02,757.64 h60
  text "UL 94V-0" at 11207.96,757.64 h60
  text "X" at 11883.02,757.64 h60
  text "RoHS" at 12019.96,757.64 h60
  text "OTHER" at 12664.36,757.64 h60
  text "PER ORDER" at 13061.42,757.64 h60
  text "ADDITIONAL REQUIREMENTS:" at 10717.46,616.64 h60
  text "MICROSECTION:" at 10792.23,501.64 h60
  text "YES" at 11697.96,501.64 h60
  text "REQUIRED" at 12559.46,345.49 h60
  text "BARE BOARD ELEC. TEST:" at 10792.23,342.64 h60
  text "NONE" at 12097.96,342.64 h60
  text "X" at 12432.46,342.64 h60
  text "PER ORDER" at 13151.46,342.64 h60
  text "MANUFACTURER'S UL:" at 10792.23,185.64 h60
  text "RAIL" at 11957.96,181.35 h60
  text "METAL" at 12449.77,181.35 h60
  text "X" at 12825,181 h60
  text "SILK" at 12961.46,181.35 h60
  text ".Layer_Name" at -38,-1627.49 h60
M11 Gerber Information:
  lines w10: -907,-1699.17 5693,-1699.17 ; -907,-1495.83 5695,-1495.83 ; -907,-1292.5 -907,-1902.5 3098,-1902.5 5695,-1902.5 5695,-1292.5 -906.5,-1292.5 -906.5,-1902.5 669,-1902.5 ; 1558,-1902.5 1558,-1292.5 ; 2825,-1495.83 2825,-1292.5 ; 3665,-1495.83 3665,-1292.5 ; 4287,-1909 4287,-1706.17
  text "ALL ARTWORK VIEWED FROM TOP SIDE" at -843.5,-1424.67 h60
  text "BOARD #:" at 1633,-1424.67 h60
  text ".PRJ_Number" at 2178.5,-1424.67 h60
  text "REV:" at 3023,-1424.67 h60
  text ".PCB_Rev" at 3314.5,-1424.67 h60
  text "SVN REV:" at 3861,-1424.67 h60
  text ".VersionControl_RevNumber" at 4367,-1424.67 h60
  text "LAYER NAME =" at -843.5,-1627.49 h60
  text "PLOT NAME =" at -843.5,-1833.34 h60
  text ".plot_File_Name" at -38,-1833.34 h60
  text "GENERATED    :" at 1635,-1833.34 h60
  text ".Print_Date" at 2504.5,-1833.34 h60
  text ".Print_Time" at 3233.5,-1833.34 h60
  text "TEXAS INSTRUMENTS" at 4498,-1833.34 h60
M12 Stackup:
  lines w5: 10754,6960.7 13576,6960.7 ; 10754,7051.8 13576,7051.8 ; 10694,6212 ccw(c10723,6212) 10723,6183 13607,6183 ccw(c13607,6212) 13636,6212 13636,7123 ccw(c13607,7123) 13607,7152 10723,7152 ccw(c10723,7123) 10694,7123 10694,6212
  text "Layer Stack Up Detail for: SV601031A.PcbDoc" at 10754,7074 h38
  text "Layer" at 10754,7017.8 h21
  text "Gerber" at 11426.84,7017.8 h21
  text "Copper" at 11823.57,7017.8 h21
  text "Dielectric" at 12254.59,7017.8 h21
  text "Dielectric" at 12700.3,7017.8 h21
  text "Dielectric" at 13228.19,7017.8 h21
  text "Name" at 10754,6975.8 h21
  text "Document" at 11426.84,6975.8 h21
  text "Thickness" at 11823.57,6975.8 h21
  text "Height" at 12254.59,6975.8 h21
  text "Material" at 12700.3,6975.8 h21
  text "Type" at 13228.19,6975.8 h21
  text "Top Solder Mask" at 10754,6915.81 h29
  text "(.GTS)" at 11426.84,6915.81 h29
  text "0.4mil" at 12254.59,6915.81 h29
  text "Solder Resist" at 12700.3,6915.81 h29
  text "Top Layer" at 10754,6831.02 h29
  text "(.GTL)" at 11426.84,6831.02 h29
  text "2.8mil" at 11823.57,6831.02 h29
  text "6mil" at 12254.59,6788.63 h29
  text "FR-4" at 12700.3,6788.63 h29
  text "Core" at 13228.19,6788.63 h29
  text "MidLayer1" at 10754,6746.23 h29
  text "(.G1)" at 11426.84,6746.23 h29
  text "2.8mil" at 11823.57,6746.23 h29
  text "13mil" at 12254.59,6703.84 h29
  text "FR-4" at 12700.3,6703.84 h29
  text "PrePreg" at 13228.19,6703.84 h29
  text "MidLayer2" at 10754,6661.44 h29
  text "(.G2)" at 11426.84,6661.44 h29
  text "2.8mil" at 11823.57,6661.44 h29
  text "6mil" at 12254.59,6619.05 h29
  text "FR-4" at 12700.3,6619.05 h29
  text "Core" at 13228.19,6619.05 h29
  text "Mid-Layer 3" at 10754,6576.66 h29
  text "(.G3)" at 11426.84,6576.66 h29
  text "2.8mil" at 11823.57,6576.66 h29
  text "13mil" at 12254.59,6534.26 h29
  text "FR-4" at 12700.3,6534.26 h29
  text "PrePreg" at 13228.19,6534.26 h29
  text "Mid-Layer 4" at 10754,6491.87 h29
  text "(.G4)" at 11426.84,6491.87 h29
  text "2.8mil" at 11823.57,6491.87 h29
  text "6mil" at 12254.59,6449.48 h29
  text "FR-4" at 12700.3,6449.48 h29
  text "Core" at 13228.19,6449.48 h29
  text "Bottom Layer" at 10754,6407.08 h29
  text "(.GBL)" at 11426.84,6407.08 h29
  text "2.8mil" at 11823.57,6407.08 h29
  text "Bottom Solder Mask" at 10754,6322.29 h29
  text "(.GBS)" at 11426.84,6322.29 h29
  text "0.4mil" at 12254.59,6322.29 h29
  text "Solder Resist" at 12700.3,6322.29 h29
  text ".Layer_Name" at -38,-1627.49 h60
M13 Component Bodies Top:
  text ".Layer_Name" at -38,-1627.49 h60
M14 Component Bodies Bottom:
  text ".Layer_Name" at -38,-1627.49 h60
M15 Courtyards Top:
  text ".Layer_Name" at -38,-1627.49 h60
M16 Courtyards Bottom:
  text ".Layer_Name" at -38,-1627.49 h60
Drill Drawing:
  text ".legend" at 4507.5,-43.5 h60
  text "Drill Table" at 4532.5,-228.5 h60
  text ".Layer_Name" at -38,-1627.49 h60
